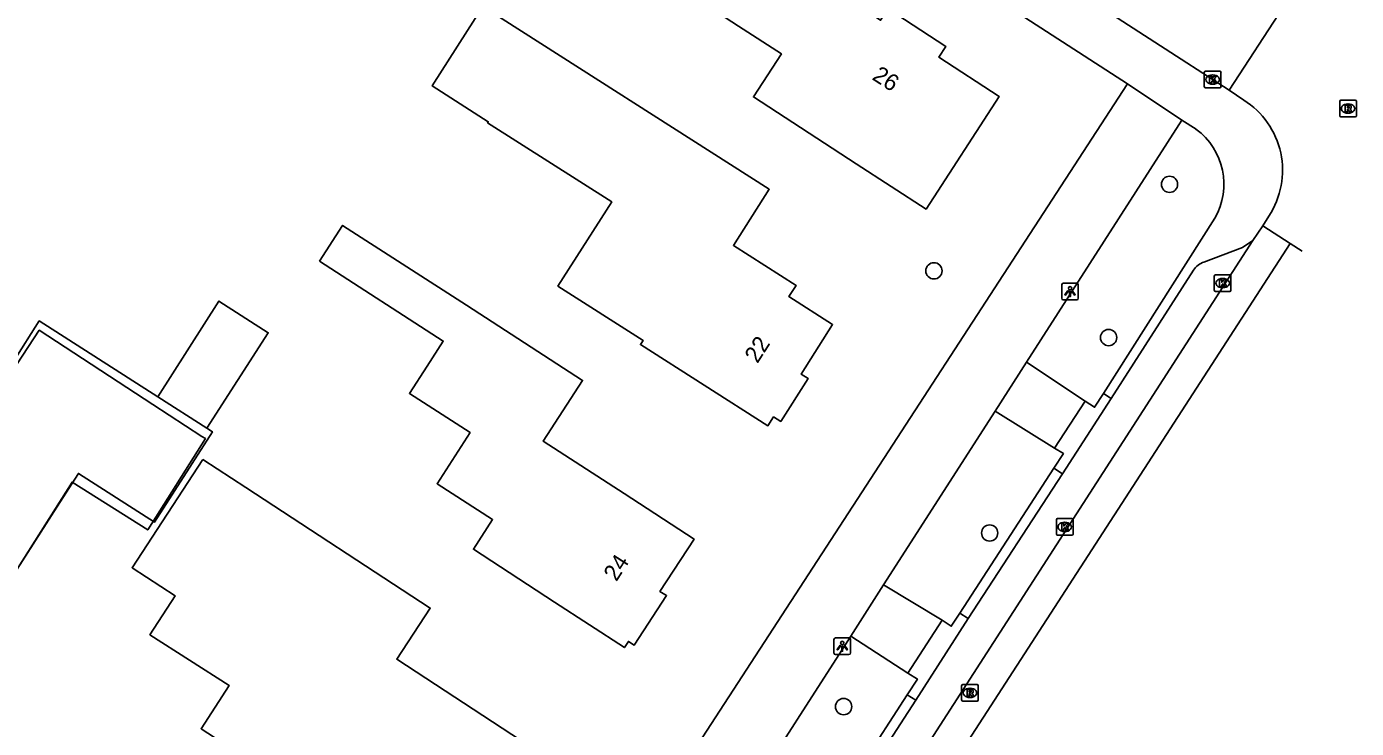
# Model space of a CAD drawing. Extents: x 161141 to 161601, y 381708 to 382245.
# Drawn here: x 161408.7 to 161488.5, y 381926.5 to 381968.7 of the extents above; entities that cross this region are included whole.
import ezdxf

# ---------------------------------------------------------------- set-up
doc = ezdxf.new("R2010")
doc.units = 0
for name, color, linetype in [('IMGEO_Boom', 7, 'Continuous'), ('IMGEO_Kolk', 7, 'Continuous'), ('IMGEO_Lichtpunt', 7, 'Continuous'), ('IMGEO_Pand', 7, 'Continuous'), ('IMGEO_Pand_nummerreeks', 7, 'Continuous'), ('IMGEO_Pand_vergunning_verleend', 7, 'Continuous'), ('IMGEO_Rijbaan_lokaal_gesloten', 7, 'Continuous'), ('IMGEO_Rijbaan_lokaal_open', 7, 'Continuous'), ('IMGEO_Rioolput', 7, 'Continuous'), ('IMGEO_Voetpad_open', 7, 'Continuous')]:
    doc.layers.add(name, color=color, linetype=linetype)

msp = doc.modelspace()

# ---------------------------------------------------------------- linework, layer by layer
at = {"layer": 'IMGEO_Boom'}
for centre in [(161477.319, 381959.197), (161463.178, 381954.004), (161473.664, 381949.997), (161466.524, 381938.263), (161457.757, 381927.835)]:
    msp.add_circle(centre, 0.489, dxfattribs=at)
at = {"layer": 'IMGEO_Kolk'}
for p, q in [((161479.408, 381965.065), (161479.408, 381965.917)), ((161479.483, 381965.991), (161480.335, 381965.991)), ((161479.896, 381965.771), (161479.921, 381965.771)), ((161480.409, 381965.917), (161480.409, 381965.065)), ((161480.335, 381964.991), (161479.483, 381964.991)), ((161479.919, 381965.211), (161479.894, 381965.211)), ((161480.008, 381952.84), (161480.008, 381953.692)), ((161480.083, 381953.766), (161480.935, 381953.766)), ((161480.496, 381953.546), (161480.521, 381953.546)), ((161481.009, 381953.692), (161481.009, 381952.84)), ((161480.935, 381952.766), (161480.083, 381952.766)), ((161480.519, 381952.986), (161480.494, 381952.986)), ((161470.529, 381938.199), (161470.529, 381939.051)), ((161470.604, 381939.125), (161471.456, 381939.125)), ((161471.53, 381939.051), (161471.53, 381938.199)), ((161471.04, 381938.345), (161471.015, 381938.345)), ((161471.017, 381938.905), (161471.042, 381938.905)), ((161471.456, 381938.125), (161470.604, 381938.125))]:
    msp.add_line(p, q, dxfattribs=at)
for points in [[(161479.408, 381965.065), (161479.408, 381965.917)], [(161479.483, 381965.991), (161480.335, 381965.991)], [(161479.729, 381965.691), (161479.852, 381965.691), (161479.852, 381965.54), (161479.982, 381965.691), (161480.146, 381965.691), (161480, 381965.54), (161480.153, 381965.291), (161480.001, 381965.291), (161479.916, 381965.455), (161479.852, 381965.388), (161479.852, 381965.291), (161479.729, 381965.291), (161479.729, 381965.691)], [(161480.409, 381965.917), (161480.409, 381965.065)], [(161480.335, 381964.991), (161479.483, 381964.991)], [(161480.008, 381952.84), (161480.008, 381953.692)], [(161480.083, 381953.766), (161480.935, 381953.766)], [(161480.329, 381953.466), (161480.452, 381953.466), (161480.452, 381953.315), (161480.582, 381953.466), (161480.746, 381953.466), (161480.6, 381953.315), (161480.753, 381953.066), (161480.601, 381953.066), (161480.516, 381953.23), (161480.452, 381953.163), (161480.452, 381953.066), (161480.329, 381953.066), (161480.329, 381953.466)], [(161481.009, 381953.692), (161481.009, 381952.84)], [(161480.935, 381952.766), (161480.083, 381952.766)], [(161470.529, 381938.199), (161470.529, 381939.051)], [(161470.604, 381939.125), (161471.456, 381939.125)], [(161471.53, 381939.051), (161471.53, 381938.199)], [(161470.85, 381938.825), (161470.973, 381938.825), (161470.973, 381938.674), (161471.103, 381938.825), (161471.267, 381938.825), (161471.121, 381938.674), (161471.274, 381938.425), (161471.122, 381938.425), (161471.037, 381938.589), (161470.973, 381938.522), (161470.973, 381938.425), (161470.85, 381938.425), (161470.85, 381938.825)], [(161471.456, 381938.125), (161470.604, 381938.125)]]:
    msp.add_lwpolyline(points, dxfattribs=at)
for centre, start, end in [((161479.485, 381965.915), 91.55205, 178.44795), ((161479.485, 381965.915), 91.55205, 178.44795), ((161480.333, 381965.915), 1.55205, 88.44795), ((161480.333, 381965.915), 1.55205, 88.44795), ((161479.485, 381965.067), 181.55205, 268.44795), ((161479.485, 381965.067), 181.55205, 268.44795), ((161480.333, 381965.067), 271.55205, 358.44795), ((161480.333, 381965.067), 271.55205, 358.44795), ((161480.085, 381953.69), 91.55205, 178.44795), ((161480.085, 381953.69), 91.55205, 178.44795), ((161480.933, 381953.69), 1.55205, 88.44795), ((161480.933, 381953.69), 1.55205, 88.44795), ((161480.085, 381952.842), 181.55205, 268.44795), ((161480.085, 381952.842), 181.55205, 268.44795), ((161480.933, 381952.842), 271.55205, 358.44795), ((161480.933, 381952.842), 271.55205, 358.44795), ((161470.606, 381939.049), 91.55205, 178.44795), ((161470.606, 381939.049), 91.55205, 178.44795), ((161471.454, 381939.049), 1.55205, 88.44795), ((161471.454, 381939.049), 1.55205, 88.44795), ((161470.606, 381938.201), 181.55205, 268.44795), ((161470.606, 381938.201), 181.55205, 268.44795), ((161471.454, 381938.201), 271.55205, 358.44795), ((161471.454, 381938.201), 271.55205, 358.44795)]:
    msp.add_arc(centre, 0.0765, start, end, dxfattribs=at)
for centre, major_axis, ratio, start_param, end_param in [((161479.895, 381965.491), (-0.387, 0.002), 0.722429, 4.712389, 7.853982), ((161479.92, 381965.491), (-0.39, 0.002), 0.717154, 1.570796, 4.712389), ((161480.495, 381953.266), (-0.387, 0.002), 0.722429, 4.712389, 7.853982), ((161480.52, 381953.266), (-0.39, 0.002), 0.717154, 1.570796, 4.712389), ((161471.016, 381938.625), (-0.387, 0.002), 0.722429, 4.712389, 7.853982), ((161471.041, 381938.625), (-0.39, 0.002), 0.717154, 1.570796, 4.712389)]:
    msp.add_ellipse(centre, major_axis=major_axis, ratio=ratio, start_param=start_param, end_param=end_param, dxfattribs=at)
at = {"layer": 'IMGEO_Lichtpunt'}
for p, q in [((161470.848, 381953.164), (161470.848, 381952.357)), ((161470.848, 381953.164), (161470.848, 381952.357)), ((161471.75, 381953.259), (161470.942, 381953.259)), ((161471.75, 381953.259), (161470.942, 381953.259)), ((161471.844, 381952.357), (161471.844, 381953.164)), ((161471.844, 381952.357), (161471.844, 381953.164)), ((161470.942, 381952.263), (161471.75, 381952.263)), ((161470.942, 381952.263), (161471.75, 381952.263)), ((161457.178, 381931.864), (161457.178, 381931.057)), ((161457.178, 381931.864), (161457.178, 381931.057)), ((161458.08, 381931.959), (161457.272, 381931.959)), ((161458.08, 381931.959), (161457.272, 381931.959)), ((161458.174, 381931.057), (161458.174, 381931.864)), ((161458.174, 381931.057), (161458.174, 381931.864)), ((161457.272, 381930.963), (161458.08, 381930.963)), ((161457.272, 381930.963), (161458.08, 381930.963))]:
    msp.add_line(p, q, dxfattribs=at)
for points in [[(161471.222, 381952.828), (161471.261, 381952.8), (161471.073, 381952.538), (161471.035, 381952.565), (161471.222, 381952.828)], [(161471.324, 381952.78), (161471.371, 381952.78), (161471.371, 381952.458), (161471.324, 381952.458), (161471.324, 381952.78)], [(161471.434, 381952.8), (161471.472, 381952.827), (161471.659, 381952.565), (161471.62, 381952.537), (161471.434, 381952.8)], [(161457.552, 381931.528), (161457.591, 381931.5), (161457.403, 381931.238), (161457.365, 381931.265), (161457.552, 381931.528)], [(161457.654, 381931.48), (161457.701, 381931.48), (161457.701, 381931.158), (161457.654, 381931.158), (161457.654, 381931.48)], [(161457.764, 381931.5), (161457.802, 381931.527), (161457.989, 381931.265), (161457.95, 381931.237), (161457.764, 381931.5)]]:
    msp.add_lwpolyline(points, dxfattribs=at)
for centre in [(161471.347, 381952.962), (161457.677, 381931.662)]:
    msp.add_circle(centre, 0.0994, dxfattribs=at)
for centre, start, end in [((161470.942, 381953.164), 90, 180), ((161470.942, 381953.164), 90, 180), ((161471.75, 381953.164), 0, 90), ((161471.75, 381953.164), 0, 90), ((161470.942, 381952.357), 180, 270), ((161470.942, 381952.357), 180, 270), ((161471.75, 381952.357), 270, 0), ((161471.75, 381952.357), 270, 360), ((161457.272, 381931.864), 90, 180), ((161457.272, 381931.864), 90, 180), ((161458.08, 381931.864), 0, 90), ((161458.08, 381931.864), 0, 90), ((161457.272, 381931.057), 180, 270), ((161457.272, 381931.057), 180, 270), ((161458.08, 381931.057), 270, 0), ((161458.08, 381931.057), 270, 360)]:
    msp.add_arc(centre, 0.0946, start, end, dxfattribs=at)
at = {"layer": 'IMGEO_Pand'}
for points in [[(161449.552, 381975.564), (161456.544, 381971.017), (161456.666, 381971.205), (161459.982, 381969.048), (161460.425, 381969.728), (161463.898, 381967.469), (161463.48, 381966.826), (161467.104, 381964.469), (161462.709, 381957.712), (161458.518, 381960.439), (161452.348, 381964.452), (161454.026, 381967.032), (161451.457, 381968.703), (161446.982, 381971.614), (161449.552, 381975.564)], [(161436.113, 381969.868), (161453.299, 381958.899), (161451.149, 381955.529), (161454.905, 381953.132), (161454.472, 381952.454), (161457.1, 381950.777), (161455.205, 381947.808), (161455.632, 381947.535), (161453.984, 381944.959), (161453.554, 381945.234), (161453.216, 381944.706), (161445.564, 381949.575), (161445.725, 381949.828), (161440.611, 381953.092), (161443.837, 381958.147), (161436.391, 381962.9), (161436.43, 381962.961), (161433.072, 381965.105), (161436.113, 381969.868)], [(161426.297, 381954.589), (161427.683, 381956.735), (161435.118, 381951.933), (161442.093, 381947.428), (161439.732, 381943.773), (161444.594, 381940.628), (161448.782, 381937.896), (161446.736, 381934.759), (161447.131, 381934.501), (161445.19, 381931.527), (161444.844, 381931.753), (161444.6, 381931.379), (161440.412, 381934.111), (161435.544, 381937.289), (161436.694, 381939.07), (161433.36, 381941.223), (161435.339, 381944.288), (161431.697, 381946.644), (161432.758, 381948.284), (161433.731, 381949.788), (161426.297, 381954.589)], [(161416.59, 381946.44), (161420.268, 381952.184), (161423.224, 381950.291), (161419.546, 381944.547)], [(161407.925, 381948.568), (161409.478, 381950.994), (161416.59, 381946.44)], [(161416.59, 381946.44), (161419.546, 381944.547)], [(161419.546, 381944.547), (161419.872, 381944.339), (161416.401, 381938.917), (161411.831, 381941.842), (161410.527, 381939.805), (161407.83, 381935.594), (161402.006, 381939.323), (161402.334, 381939.835)], [(161419.303, 381942.671), (161421.878, 381940.989), (161432.947, 381933.757), (161430.94, 381930.685), (161438.43, 381925.79), (161433.961, 381918.951), (161429.542, 381921.839), (161428.584, 381920.374), (161422.791, 381924.16), (161419.192, 381926.512), (161420.883, 381929.103), (161416.127, 381932.149), (161417.632, 381934.492), (161415.057, 381936.174), (161419.303, 381942.671)]]:
    msp.add_lwpolyline(points, dxfattribs=at)
at = {"layer": 'IMGEO_Pand_vergunning_verleend'}
msp.add_lwpolyline([(161402.006, 381939.323), (161402.334, 381939.835), (161407.925, 381948.568), (161408.156, 381948.417), (161409.477, 381950.435), (161416.288, 381945.978), (161419.231, 381944.052), (161419.455, 381943.928), (161415.992, 381938.447), (161411.447, 381941.319), (161407.83, 381935.594), (161402.006, 381939.323)], dxfattribs=at)
at = {"layer": 'IMGEO_Rijbaan_lokaal_gesloten'}
for points in [[(161482.323, 381955.826), (161482.913, 381956.712)], [(161482.323, 381955.826), (161445.595, 381898.855), (161442.845, 381894.672)], [(161484.559, 381955.638), (161443.88, 381892.8)]]:
    msp.add_lwpolyline(points, dxfattribs=at)
at = {"layer": 'IMGEO_Rijbaan_lokaal_open'}
for points in [[(161480.897, 381964.849), (161471.977, 381970.646), (161450.889, 381984.377), (161443.856, 381988.93), (161430.314, 381997.713), (161423.318, 382002.239), (161408.287, 382012.005), (161402.555, 382015.697), (161398.439, 382018.395), (161388.068, 382025.069), (161381.679, 382029.228), (161366.307, 382039.161), (161359.944, 382043.32), (161345.442, 382052.667), (161339.032, 382056.795), (161328.504, 382063.628), (161325.321, 382065.668), (161306.338, 382077.878)], [(161484.169, 381969.847), (161480.897, 381964.849)], [(161480.897, 381964.849), (161481.77, 381964.253)], [(161483.28, 381957.292), (161482.913, 381956.712)], [(161482.913, 381956.712), (161484.559, 381955.638)], [(161485.274, 381955.176), (161484.559, 381955.638)]]:
    msp.add_lwpolyline(points, dxfattribs=at)
msp.add_arc((161479.13, 381960.036), 4.975, 326.52757, 57.95072, dxfattribs=at)
at = {"layer": 'IMGEO_Rioolput'}
for p, q in [((161487.535, 381963.32), (161487.535, 381964.172)), ((161487.61, 381964.246), (161488.462, 381964.246)), ((161488.023, 381964.026), (161488.048, 381964.026)), ((161488.536, 381964.172), (161488.536, 381963.32)), ((161488.462, 381963.246), (161487.61, 381963.246)), ((161488.046, 381963.466), (161488.021, 381963.466)), ((161464.842, 381928.235), (161464.842, 381929.087)), ((161464.917, 381929.161), (161465.769, 381929.161)), ((161465.33, 381928.941), (161465.355, 381928.941)), ((161465.843, 381929.087), (161465.843, 381928.235)), ((161465.769, 381928.161), (161464.917, 381928.161)), ((161465.353, 381928.381), (161465.328, 381928.381))]:
    msp.add_line(p, q, dxfattribs=at)
for points in [[(161487.535, 381963.32), (161487.535, 381964.172)], [(161487.61, 381964.246), (161488.462, 381964.246)], [(161488.124, 381963.944), (161487.872, 381963.946), (161487.872, 381963.546)], [(161488.05, 381963.865), (161487.996, 381963.865), (161487.996, 381963.784)], [(161487.996, 381963.784), (161488.048, 381963.784)], [(161488.536, 381964.172), (161488.536, 381963.32)], [(161488.462, 381963.246), (161487.61, 381963.246)], [(161487.872, 381963.546), (161487.996, 381963.546), (161487.996, 381963.708), (161488.007, 381963.708)], [(161488.054, 381963.679), (161488.125, 381963.546), (161488.265, 381963.546), (161488.2, 381963.672)], [(161464.842, 381928.235), (161464.842, 381929.087)], [(161464.917, 381929.161), (161465.769, 381929.161)], [(161465.431, 381928.859), (161465.179, 381928.861), (161465.179, 381928.461)], [(161465.357, 381928.78), (161465.303, 381928.78), (161465.303, 381928.699)], [(161465.303, 381928.699), (161465.355, 381928.699)], [(161465.843, 381929.087), (161465.843, 381928.235)], [(161465.769, 381928.161), (161464.917, 381928.161)], [(161465.179, 381928.461), (161465.303, 381928.461), (161465.303, 381928.623), (161465.314, 381928.623)], [(161465.361, 381928.594), (161465.432, 381928.461), (161465.572, 381928.461), (161465.507, 381928.587)]]:
    msp.add_lwpolyline(points, dxfattribs=at)
for centre, radius, start, end in [((161487.612, 381964.17), 0.0765, 91.55205, 178.44795), ((161487.612, 381964.17), 0.0765, 91.55205, 178.44795), ((161488.032, 381963.973), 0.19, 274.7715, 282.96867), ((161488.056, 381963.769), 0.0964, 77.00612, 93.18647), ((161488.07, 381963.826), 0.0378, 276.66336, 79.67722), ((161488.123, 381963.834), 0.109, 350.36119, 89.41601), ((161488.121, 381963.834), 0.112, 277.58423, 350.98172), ((161488.46, 381964.17), 0.0765, 1.55205, 88.44795), ((161488.46, 381964.17), 0.0765, 1.55205, 88.44795), ((161487.612, 381963.322), 0.0765, 181.55205, 268.44795), ((161487.612, 381963.322), 0.0765, 181.55205, 268.44795), ((161488.006, 381963.655), 0.0533, 26.02933, 88.69889), ((161488.105, 381963.619), 0.108, 29.51342, 73.79051), ((161488.46, 381963.322), 0.0765, 271.55205, 358.44795), ((161488.46, 381963.322), 0.0765, 271.55205, 358.44795), ((161464.919, 381929.085), 0.0765, 91.55205, 178.44795), ((161464.919, 381929.085), 0.0765, 91.55205, 178.44795), ((161465.339, 381928.888), 0.19, 274.7715, 282.96867), ((161465.363, 381928.684), 0.0964, 77.00612, 93.18647), ((161465.377, 381928.741), 0.0378, 276.66336, 79.67722), ((161465.43, 381928.749), 0.109, 350.36119, 89.41601), ((161465.428, 381928.749), 0.112, 277.58423, 350.98172), ((161465.767, 381929.085), 0.0765, 1.55205, 88.44795), ((161465.767, 381929.085), 0.0765, 1.55205, 88.44795), ((161464.919, 381928.237), 0.0765, 181.55205, 268.44795), ((161464.919, 381928.237), 0.0765, 181.55205, 268.44795), ((161465.313, 381928.57), 0.0533, 26.02933, 88.69889), ((161465.412, 381928.534), 0.108, 29.51342, 73.79051), ((161465.767, 381928.237), 0.0765, 271.55205, 358.44795), ((161465.767, 381928.237), 0.0765, 271.55205, 358.44795)]:
    msp.add_arc(centre, radius, start, end, dxfattribs=at)
for centre, major_axis, ratio, start_param, end_param in [((161488.022, 381963.746), (-0.387, 0.002), 0.722429, 4.712389, 7.853982), ((161488.047, 381963.746), (-0.39, 0.002), 0.717154, 1.570796, 4.712389), ((161465.329, 381928.661), (-0.387, 0.002), 0.722429, 4.712389, 7.853982), ((161465.354, 381928.661), (-0.39, 0.002), 0.717154, 1.570796, 4.712389)]:
    msp.add_ellipse(centre, major_axis=major_axis, ratio=ratio, start_param=start_param, end_param=end_param, dxfattribs=at)
at = {"layer": 'IMGEO_Voetpad_open'}
for points in [[(161474.804, 381965.241), (161421.048, 382000), (161306.066, 382074.349)], [(161430.666, 381897.334), (161474.804, 381965.241)], [(161474.804, 381965.241), (161478.068, 381963.057)], [(161468.743, 381948.527), (161478.068, 381963.057)], [(161478.068, 381963.057), (161478.909, 381962.515)], [(161480.039, 381957.163), (161473.355, 381946.644)], [(161479.385, 381954.532), (161481.705, 381955.398), (161482.323, 381955.826)], [(161473.808, 381946.346), (161478.765, 381954.039)], [(161468.743, 381948.527), (161466.851, 381945.579)], [(161472.261, 381946.18), (161468.743, 381948.527)], [(161473.808, 381946.346), (161470.887, 381941.819)], [(161472.261, 381946.18), (161472.824, 381945.809), (161473.355, 381946.644)], [(161473.355, 381946.644), (161473.808, 381946.346)], [(161460.162, 381935.157), (161466.851, 381945.579)], [(161466.851, 381945.579), (161470.422, 381943.36)], [(161470.422, 381943.36), (161472.261, 381946.18)], [(161470.422, 381943.36), (161470.955, 381943.032), (161470.374, 381942.161)], [(161470.374, 381942.161), (161464.734, 381933.448)], [(161470.887, 381941.819), (161465.235, 381933.121)], [(161470.887, 381941.819), (161470.374, 381942.161)], [(161458.183, 381932.073), (161460.162, 381935.157)], [(161463.677, 381933.019), (161460.162, 381935.157)], [(161464.734, 381933.448), (161464.222, 381932.663), (161463.677, 381933.019)], [(161464.734, 381933.448), (161465.235, 381933.121)], [(161461.612, 381929.854), (161463.677, 381933.019)], [(161465.235, 381933.121), (161462.089, 381928.215)], [(161451.6, 381921.815), (161458.183, 381932.073)], [(161458.183, 381932.073), (161461.612, 381929.854)], [(161461.612, 381929.854), (161462.19, 381929.494), (161461.576, 381928.548)], [(161461.576, 381928.548), (161456.096, 381920.062)], [(161462.089, 381928.215), (161456.613, 381919.75)], [(161461.576, 381928.548), (161462.089, 381928.215)]]:
    msp.add_lwpolyline(points, dxfattribs=at)
for centre, radius, start, end in [((161476.493, 381959.21), 4.094, 330.00812, 53.83609), ((161479.728, 381953.464), 1.122, 107.81909, 149.16163)]:
    msp.add_arc(centre, radius, start, end, dxfattribs=at)

# ---------------------------------------------------------------- texts
at = {"layer": 'IMGEO_Pand_nummerreeks'}
for s, rotation, p in [('26', 327.16446, (161459.413, 381965.529)), ('22', 57.39318, (161452.588, 381948.401)), ('24', 57.31297, (161444.124, 381935.303))]:
    msp.add_text(s, height=1, rotation=rotation, dxfattribs=at).set_placement(p)

doc.saveas('drawing.dxf')
